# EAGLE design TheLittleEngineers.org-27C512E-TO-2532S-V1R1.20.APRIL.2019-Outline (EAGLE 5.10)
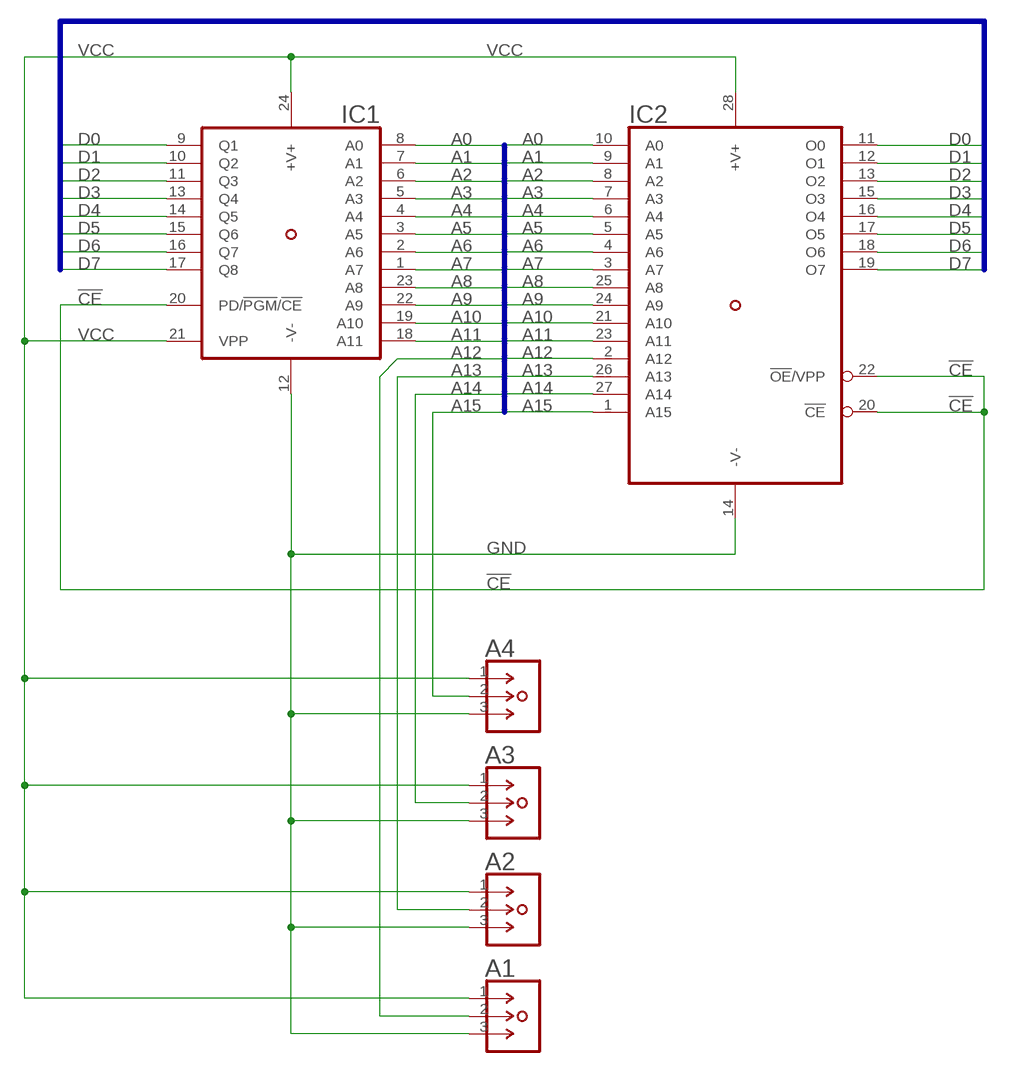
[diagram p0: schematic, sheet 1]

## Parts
A1  1X03-STAGGERED-S  [1X03-STAGGERED]
A2  1X03-STAGGERED-S  [1X03-STAGGERED]
A3  1X03-STAGGERED-S  [1X03-STAGGERED]
A4  1X03-STAGGERED-S  [1X03-STAGGERED]
IC1  TMS2532-NO  [DIL24-6-NO-OUTLINE]
IC2  27C512D-NO  [DIL28-6-NO-OUTLINE]

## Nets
!CE: IC1.20(PD/!PGM!/!CE) IC2.20(!CE) IC2.22(!OE!/VPP)
A0: IC1.8(A0) IC2.10(A0)
A1: IC1.7(A1) IC2.9(A1)
A2: IC1.6(A2) IC2.8(A2)
A3: IC1.5(A3) IC2.7(A3)
A4: IC1.4(A4) IC2.6(A4)
A5: IC1.3(A5) IC2.5(A5)
A6: IC1.2(A6) IC2.4(A6)
A7: IC1.1(A7) IC2.3(A7)
A8: IC1.23(A8) IC2.25(A8)
A9: IC1.22(A9) IC2.24(A9)
A10: IC1.19(A10) IC2.21(A10)
A11: IC1.18(A11) IC2.23(A11)
A12: A1.2 IC2.2(A12)
A13: A2.2 IC2.26(A13)
A14: A3.2 IC2.27(A14)
A15: A4.2 IC2.1(A15)
D0: IC1.9(Q1) IC2.11(O0)
D1: IC1.10(Q2) IC2.12(O1)
D2: IC1.11(Q3) IC2.13(O2)
D3: IC1.13(Q4) IC2.15(O3)
D4: IC1.14(Q5) IC2.16(O4)
D5: IC1.15(Q6) IC2.17(O5)
D6: IC1.16(Q7) IC2.18(O6)
D7: IC1.17(Q8) IC2.19(O7)
GND [power]: A1.3 A2.3 A3.3 A4.3 IC1.12(-V-) IC2.14(-V-)
VCC [power]: A1.1 A2.1 A3.1 A4.1 IC1.21(VPP) IC1.24(+V+) IC2.28(+V+)

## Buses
D[0..7]
A[0..15]

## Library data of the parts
A1-A4 = TheLittleEngineers.org-27C512E-TO-2532S-V1R0.20.APRIL.2019:1X03-STAGGERED: 3-Pin SIP Header Copyright ©07 Jan 2013, by: Robert "The R.A.T." Allen Turner http://www.TheLittleEngineers.org/ TheLittleEngineers@outlook.com OurLittleEngineers@gMail.com You may use these components in your own projects, however, please take note that we CANNOT guarantee the accuracy of these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
IC1 = TheLittleEngineers.org-27C512E-TO-2532S-V1R0.20.APRIL.2019:TMS2532: TMS2532 Copyright ©07 Jan 2013, by: Robert "The R.A.T." Allen Turner http://www.TheLittleEngineers.org/ TheLittleEngineers@outlook.com OurLittleEngineers@gMail.com You may use these components in your own projects, however, please take note that we CANNOT guarantee the accuracy of these components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
IC2 = TheLittleEngineers.org-27C512E-TO-2532S-V1R0.20.APRIL.2019:27C512D: 27C512D Copyright ©07 Jan 2013, by: Robert "The R.A.T." Allen Turner http://www.TheLittleEngineers.org/ TheLittleEngineers@outlook.com OurLittleEngineers@gMail.com You may use these components in your own projects, however, please take note that we CANNOT guarantee the accuracy of these components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

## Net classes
0 default: width 0.203 mm, clearance 0.203 mm
1 power: width 0.381 mm, clearance 0.203 mm

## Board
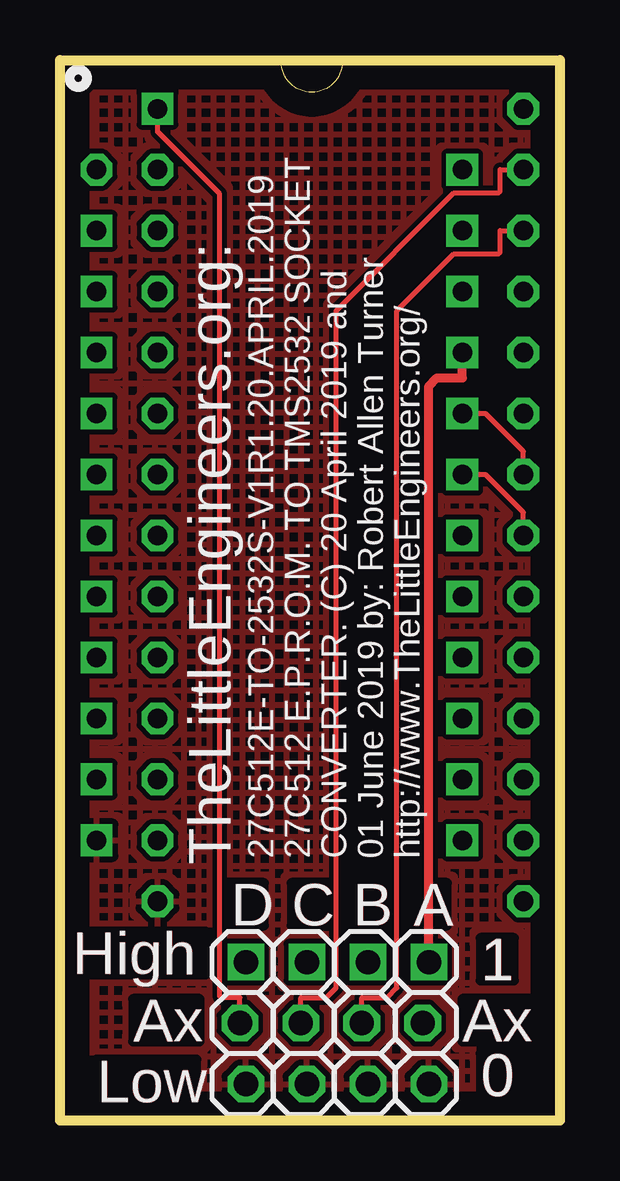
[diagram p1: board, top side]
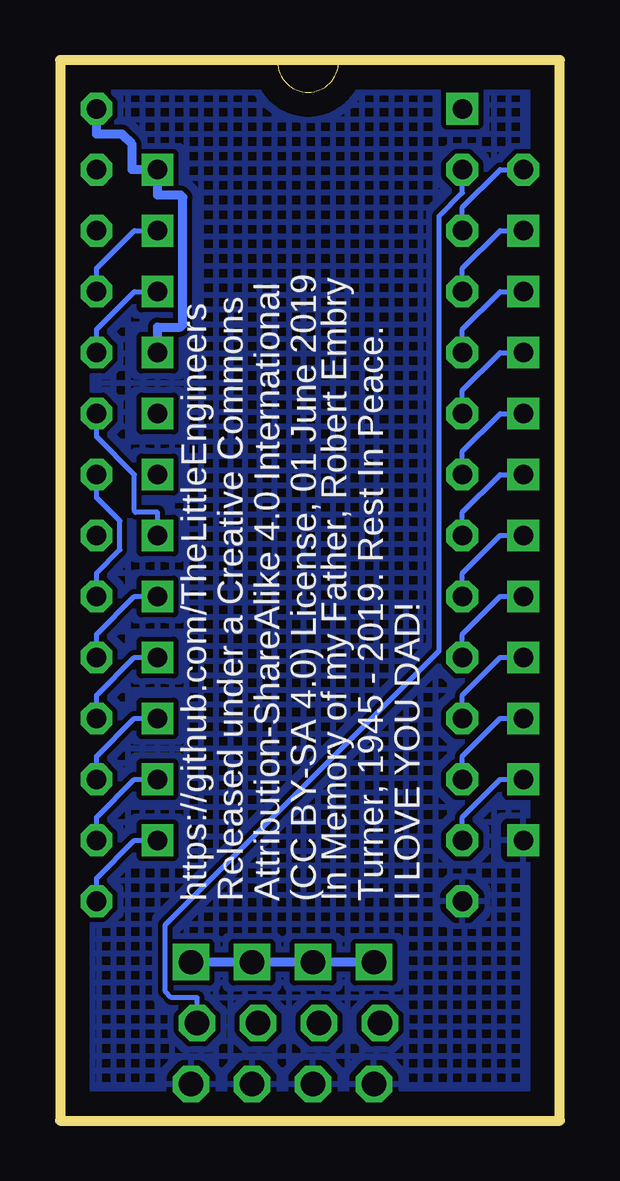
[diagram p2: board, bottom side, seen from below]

Size 20.83 x 44.2 mm. Coordinates in mm from the lower left corner, seen from the top.
Outline: 0,44.2 20.83,44.2 20.83,0 0,0 0,44.2
Copper layers (1*16): Top 0.035mm / dielectric 1.5mm / Bottom 0.035mm
Design rules "default": minimum track width 10mil, minimum drill 24mil, track to track 8mil, track to pad 8mil, pad to pad 8mil, via to via 8mil, smd to smd 8mil, copper to edge 40mil, drill to drill 8mil, minimum pad ring 10mil, minimum via ring 8mil, stop-mask expansion 4mil, vias tented up to drill 0mil, thermal gap 10mil

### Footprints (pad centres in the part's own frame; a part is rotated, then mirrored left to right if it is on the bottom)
1X03-STAGGERED = drill 1.016 square: 1 -2.54,0.127 | drill 1.016 octagon: 2 0,-0.127; 3 2.54,0.127
DIL24-6-NO-OUTLINE = drill 0.813 octagon: 1 -13.97,-7.62 | drill 0.813 square: 2 -11.43,-7.62; 3 -8.89,-7.62; 4 -6.35,-7.62; 5 -3.81,-7.62; 6 -1.27,-7.62; 7 1.27,-7.62; 8 3.81,-7.62; 9 6.35,-7.62; 10 8.89,-7.62; 11 11.43,-7.62; 12 13.97,-7.62; 13 13.97,7.62; 14 11.43,7.62; 15 8.89,7.62; 16 6.35,7.62; 17 3.81,7.62; 18 1.27,7.62; 19 -1.27,7.62; 20 -3.81,7.62; 21 -6.35,7.62; 22 -8.89,7.62; 23 -11.43,7.62; 24 -13.97,7.62
DIL28-6-NO-OUTLINE = drill 0.813 square: 1 -16.51,-7.62 | drill 0.813 octagon: 2 -13.97,-7.62; 3 -11.43,-7.62; 4 -8.89,-7.62; 5 -6.35,-7.62; 6 -3.81,-7.62; 7 -1.27,-7.62; 8 1.27,-7.62; 9 3.81,-7.62; 10 6.35,-7.62; 11 8.89,-7.62; 12 11.43,-7.62; 13 13.97,-7.62; 14 16.51,-7.62; 15 16.51,7.62; 16 13.97,7.62; 17 11.43,7.62; 18 8.89,7.62; 19 6.35,7.62; 20 3.81,7.62; 21 1.27,7.62; 22 -1.27,7.62; 23 -3.81,7.62; 24 -6.35,7.62; 25 -8.89,7.62; 26 -11.43,7.62; 27 -13.97,7.62; 28 -16.51,7.62

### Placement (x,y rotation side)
A1  15.24,4.06 270 top
A2  12.7,4.06 270 top
A3  10.16,4.06 270 top
A4  7.62,4.06 270 top
IC1  9.14,25.65 270 top
IC2  11.68,25.65 270 top
U$1  [OUTLINE]  1.52,0.25 0 top

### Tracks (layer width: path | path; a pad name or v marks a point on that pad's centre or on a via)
!CE
  Top 0.203: IC1.20 17.73,29.46 19.3,27.89 IC2.22
  Bottom 0.203: IC2.22 19.3,25.96 18.34,24.99 18.34,23.78 19.3,22.81 IC2.20
A0
  Bottom 0.203: IC1.8 2.49,21.84 4.06,20.27 IC2.10
A1
  Bottom 0.203: IC1.7 2.49,24.38 4.06,22.81 IC2.9
A2
  Bottom 0.203: IC1.6 2.49,26.92 4.06,25.35 IC2.8
A3
  Bottom 0.203: IC1.5 2.49,29.46 4.06,27.89 IC2.7
A4
  Bottom 0.203: IC1.4 2.49,32 4.06,30.43 IC2.6
A5
  Bottom 0.203: IC1.3 2.49,34.54 4.06,32.97 IC2.5
A6
  Bottom 0.203: IC1.2 2.49,37.08 4.06,35.51 IC2.4
A7
  Bottom 0.203: IC1.1 2.49,39.62 4.06,38.05 IC2.3
A8
  Bottom 0.203: IC1.23 17.73,37.08 19.3,35.51 IC2.25
A9
  Bottom 0.203: IC1.22 17.73,34.54 19.3,32.97 IC2.24
A10
  Top 0.203: IC1.19 17.73,26.92 19.3,25.35 IC2.21
A11
  Bottom 0.203: IC1.18 16.76,25.35 17.68,25.35 17.73,25.41 17.73,26.92 19.3,28.5 IC2.23
A12
  Bottom 0.203: A1.2 15.11,5.13 16.18,5.13 16.44,5.39 16.44,8.17 5.03,19.58 5.03,37.69 4.06,38.66 IC2.2
A13
  Top 0.203: A2.2 12.57,5.13 13.64,5.13 14.04,5.53 14.04,33.75 16.41,36.12 18.28,36.12 18.34,36.17 18.34,37.08 IC2.26
A14
  Top 0.203: A3.2 10.03,5.13 11.1,5.13 11.5,5.53 11.5,33.75 16.41,38.66 18.28,38.66 18.34,38.71 18.34,39.62 IC2.27
A15
  Top 0.203: A4.2 7.49,5.13 6.7,5.13 6.65,5.19 6.65,38.61 4.06,41.2 IC2.1
D0
  Bottom 0.203: IC1.9 2.49,19.3 4.06,17.73 IC2.11
D1
  Bottom 0.203: IC1.10 2.49,16.76 4.06,15.19 IC2.12
D2
  Bottom 0.203: IC1.11 2.49,14.22 4.06,12.65 IC2.13
D3
  Bottom 0.203: IC1.13 17.73,11.68 19.3,10.11 IC2.15
D4
  Bottom 0.203: IC1.14 17.73,14.22 19.3,12.65 IC2.16
D5
  Bottom 0.203: IC1.15 17.73,16.76 19.3,15.19 IC2.17
D6
  Bottom 0.203: IC1.16 17.73,19.3 19.3,17.73 IC2.18
D7
  Bottom 0.203: IC1.17 17.73,21.84 19.3,20.27 IC2.19
GND
  pour Top (hatched): 0,44.2 20.83,44.2 20.83,0 0,0
  pour Bottom (hatched): 0,44.2 20.83,44.2 20.83,0 0,0
VCC
  Top 0.381: IC1.21 16.76,30.95 15.71,30.95 15.37,30.61 A1.1
  Bottom 0.381: IC2.28 19.3,41.11 18.25,41.11 17.82,40.68 17.82,39.62 IC1.24 16.76,38.57 15.82,38.57 15.71,38.46 15.71,33.17 15.82,33.06 16.76,33.06 IC1.21 | A1.1 A2.1 A3.1 A4.1
(copper drawn outside any net)
  shapes: Top circle x1

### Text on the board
Top: D | C | B | A | High | 1 | Ax | Ax | Low | 0
tPlace: 27C512E-TO-2532S-V1R1.20.APRIL.2019 | 27C512 E.P.R.O.M. TO TMS2532 SOCKET | CONVERTER. (C) 20 April 2019 and | 01 June 2019 by: Robert Allen Turner | http://www.TheLittleEngineers.org/ | TheLittleEngineers.org: | D | C | B | A | High | 1 | Ax | Ax | Low | 0
bPlace: I LOVE YOU DAD! | Turner, 1945 - 2019. Rest In Peace. | In Memory of my Father, Robert Embry | (CC BY-SA 4.0) License, 01 June 2019 | Attribution-ShareAlike 4.0 International | Released under a Creative Commons | https://github.com/TheLittleEngineers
